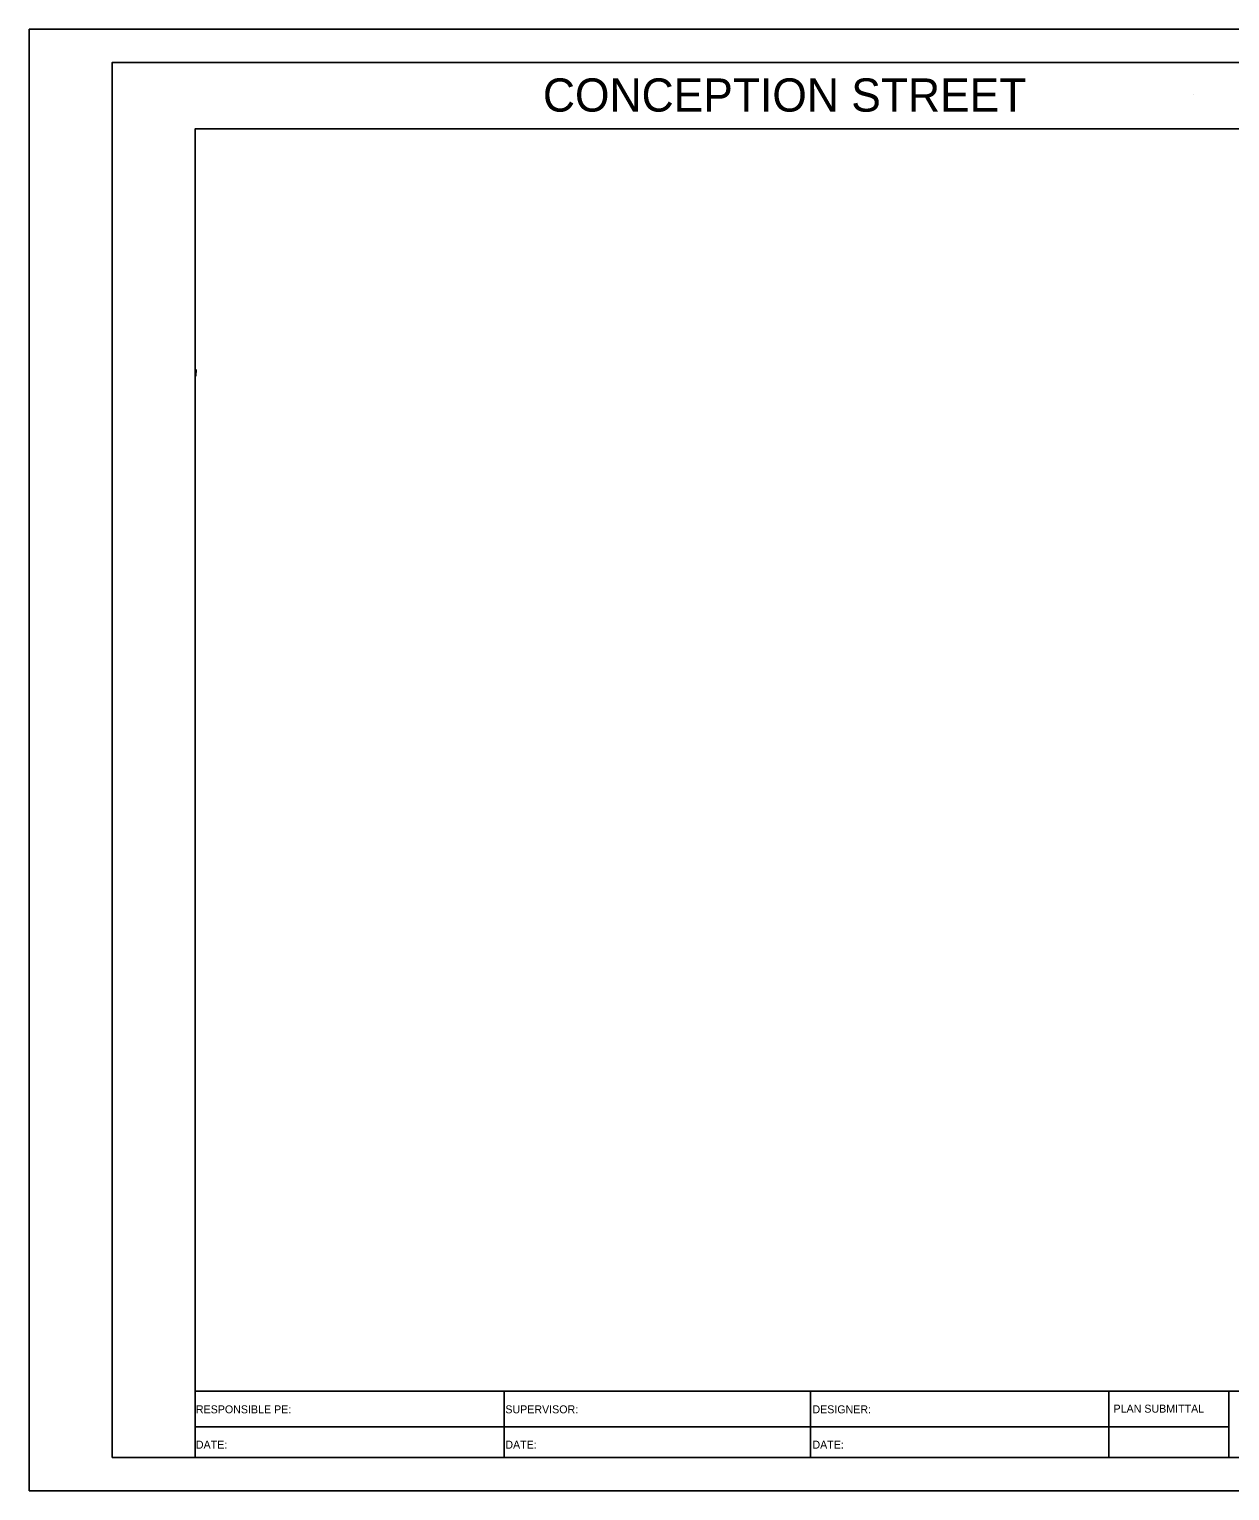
# Model space of a CAD drawing. Extents: x 1797478 to 1802456, y 246529 to 250952.
# Drawn here: x 1802116 to 1802296.8, y 250064.4 to 250284.4 of the extents above; entities that cross this region are included whole.
import ezdxf

# ---------------------------------------------------------------- set-up
doc = ezdxf.new("R2010")
doc.units = 0
for name, color, linetype in [('2', 7, 'Continuous'), ('ANNO-SHT', 7, 'Continuous'), ('ANNO-TXT', 7, 'Continuous'), ('AXIS', 7, 'Continuous'), ('DRAINAGE', 7, 'Continuous'), ('Level 1', 7, 'Continuous'), ('Level 62', 7, 'Continuous'), ('SHT-BDR', 7, 'Continuous'), ('SHT-BNDRY', 7, 'Continuous')]:
    doc.layers.add(name, color=color, linetype=linetype)

# ---------------------------------------------------------------- blocks, each defined once
blk = doc.blocks.new('SC47208')
at = {"layer": 'Level 1'}
blk.add_line((0, 0), (0, 0), dxfattribs=at)

msp = doc.modelspace()

# ---------------------------------------------------------------- linework, layer by layer
at = {"layer": '2'}
msp.add_lwpolyline([(1802141.12, 250233.21), (1802141.1, 250232.21)], dxfattribs=at)
msp.add_lwpolyline([(1802141.12, 250233.21), (1802141.1, 250232.21)], dxfattribs=at)
at = {"layer": 'AXIS'}
msp.add_line((1802141, 250189.42), (1802141, 250189.43), dxfattribs=at)
at = {"layer": 'Level 62'}
msp.add_lwpolyline([(1802116, 250064.42), (1802456, 250064.42), (1802456, 250284.42), (1802116, 250284.42)], close=True, dxfattribs=at)
at = {"layer": 'SHT-BDR'}
msp.add_lwpolyline([(1802141, 250079.43), (1802441, 250079.43), (1802441, 250269.43), (1802141, 250269.43)], close=True, dxfattribs=at)
at = {"layer": 'SHT-BNDRY'}
for p, q in [((1802141, 250069.42), (1802141, 250079.43)), ((1802187.52, 250079.43), (1802187.52, 250069.42)), ((1802233.67, 250069.42), (1802233.67, 250079.43)), ((1802278.59, 250069.42), (1802278.59, 250079.43)), ((1802296.63, 250069.42), (1802296.63, 250079.43)), ((1802141, 250074.03), (1802296.63, 250074.03))]:
    msp.add_line(p, q, dxfattribs=at)
msp.add_lwpolyline([(1802128.5, 250069.42), (1802451, 250069.42), (1802451, 250279.42), (1802128.5, 250279.42)], close=True, dxfattribs=at)

# ---------------------------------------------------------------- block references
at = {"layer": 'DRAINAGE', "xscale": 0.2, "yscale": 0.20000000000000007, "rotation": -116.41666666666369}
msp.add_blockref('SC47208', (1802291.32, 250274.62), dxfattribs=at)
msp.add_blockref('SC47208', (1802291.32, 250274.62), dxfattribs=at)

# ---------------------------------------------------------------- texts
at = {"layer": 'ANNO-SHT'}
msp.add_text('             CONCEPTION STREET             ', height=4.9995, rotation=360, dxfattribs=at).set_placement((1802169.21, 250272.02))
at = {"layer": 'ANNO-TXT'}
for s, p in [('RESPONSIBLE PE:', (1802141.1, 250076.08)), ('SUPERVISOR:', (1802187.7, 250076.08)), ('DESIGNER:', (1802233.94, 250076.08)), ('PLAN SUBMITTAL', (1802279.28, 250076.18)), ('DATE:', (1802141.1, 250070.76)), ('DATE:', (1802187.7, 250070.76)), ('DATE:', (1802233.94, 250070.76))]:
    msp.add_text(s, height=1.2, rotation=360, dxfattribs=at).set_placement(p)

doc.saveas('drawing.dxf')
